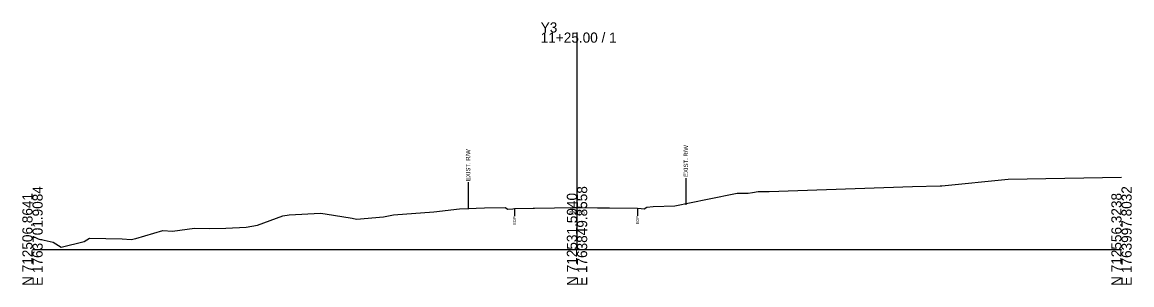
# Model space of a CAD drawing. Extents: x -26 to 2903, y -10 to 5022.
# Drawn here: x 1297.2 to 1602.8, y -9.7 to 62.7 of the extents above; entities that cross this region are included whole.
import ezdxf

# ---------------------------------------------------------------- set-up
doc = ezdxf.new("R2010")
doc.units = 0
for name, color, linetype in [('Default', 7, 'Continuous'), ('Exist Cross Section Cell', 7, 'Continuous'), ('Exist XS Center Line Elevation Label', 7, 'Continuous'), ('Exist XS Ground Line', 7, 'Continuous'), ('Old_Level_10', 7, 'Continuous')]:
    doc.layers.add(name, color=color, linetype=linetype)

msp = doc.modelspace()

# ---------------------------------------------------------------- linework, layer by layer
at = {"layer": 'Exist Cross Section Cell'}
for p, q in [((1450, 0), (1450, 59.81)), ((1300, 0), (1450, 0)), ((1450, 0), (1600, 0))]:
    msp.add_line(p, q, dxfattribs=at)
at = {"layer": 'Exist XS Ground Line'}
msp.add_lwpolyline([(1300, 3.41), (1300.62, 3.42), (1301.57, 2.99), (1305.65, 2.1), (1307.89, 0.64), (1314.25, 2.25), (1315.73, 3.19), (1324.68, 2.98), (1327.22, 2.8), (1328.43, 3.09), (1335.91, 5.26), (1338.57, 5.12), (1344.59, 5.87), (1348.71, 5.85), (1353.28, 5.89), (1358.85, 6.22), (1361.97, 6.75), (1368.99, 9.32), (1370.66, 9.59), (1379.35, 10.06), (1380.64, 9.87), (1388.03, 8.64), (1389.27, 8.42), (1396.72, 9), (1399.41, 9.54), (1410.53, 10.37), (1417.64, 11.22), (1424.49, 11.5), (1430.22, 11.65), (1430.95, 11.19), (1432.33, 11.27), (1432.74, 11.29), (1437.9, 11.38), (1438.33, 11.38), (1443.78, 11.49), (1448.75, 11.6), (1450, 11.6), (1451.03, 11.6), (1455.64, 11.53), (1458.95, 11.48), (1466.62, 11.39), (1467.68, 11.32), (1468.46, 11.26), (1469.2, 11.7), (1471, 11.92), (1476.92, 12.04), (1485.97, 13.93), (1494.11, 15.59), (1497.12, 15.59), (1498.32, 15.78), (1499.87, 16.05), (1502.96, 16.05), (1542.4, 17.41), (1550.06, 17.56), (1550.5, 17.57), (1568.75, 19.44), (1600, 19.94)], dxfattribs=at)
at = {"layer": 'Old_Level_10'}
for p, q in [((1420, 18.56), (1420, 11.16)), ((1480, 19.72), (1480, 12.32)), ((1432.76, 11.29), (1432.76, 9.24)), ((1466.68, 11.38), (1466.68, 9.33))]:
    msp.add_line(p, q, dxfattribs=at)

# ---------------------------------------------------------------- texts
at = {"layer": 'Default'}
msp.add_text('-', height=0.0001, dxfattribs=at).set_placement((1300, 0))
at = {"layer": 'Exist Cross Section Cell'}
for s, p in [('Y3', (1440, 59.81)), ('11+25.00 / 1', (1440, 57.01))]:
    msp.add_text(s, height=2.8, dxfattribs=at).set_placement(p)
for s, p in [('N 712506.8641', (1300, -10)), ('E 1763701.9084', (1302.8, -10)), ('N 712531.5940', (1450, -10)), ('E 1763849.8558', (1452.8, -10)), ('N 712556.3238', (1600, -10)), ('E 1763997.8032', (1602.8, -10))]:
    msp.add_text(s, height=2.8, rotation=90, dxfattribs=at).set_placement(p)
at = {"layer": 'Exist XS Center Line Elevation Label'}
msp.add_text('806.60', height=1, dxfattribs=at).set_placement((1447.85, 9.6))
at = {"layer": 'Old_Level_10'}
for s, height, p in [('EXIST. R/W', 1.181, (1480.59, 20.02)), ('EXIST. R/W', 1.181, (1420.59, 18.87)), ('EOP', 0.787, (1433.16, 6.84)), ('EOP', 0.787, (1467.07, 6.94))]:
    msp.add_text(s, height=height, rotation=90, dxfattribs=at).set_placement(p)

doc.saveas('drawing.dxf')
